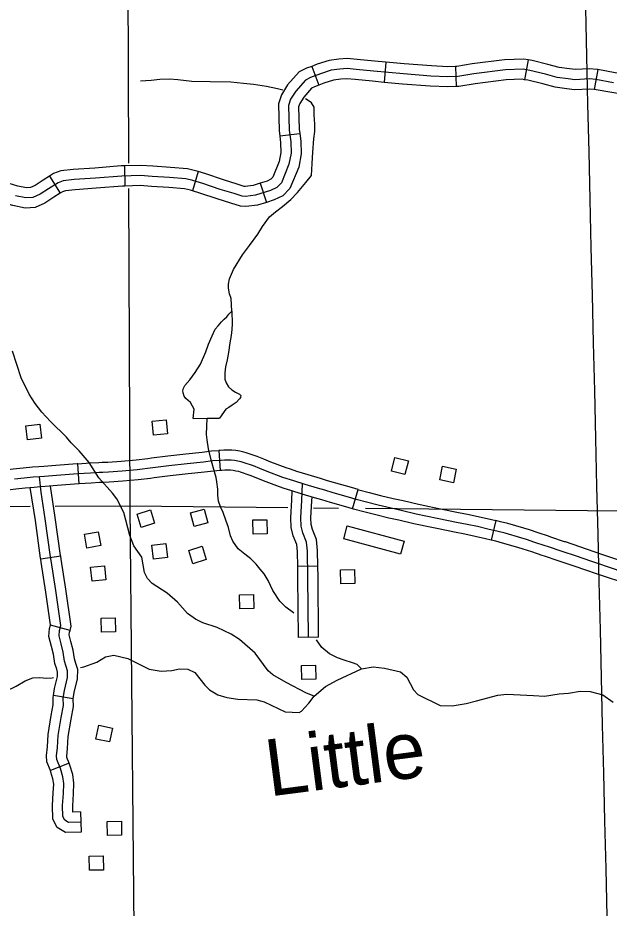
# Model space of a CAD drawing. Extents: x -19 to 366, y -4 to 359.
# Drawn here: x 134.232 to 135.065, y 193.481 to 194.735 of the extents above; entities that cross this region are included whole.
import ezdxf

# ---------------------------------------------------------------- set-up
doc = ezdxf.new("R2010")
doc.units = 0
for name, color, linetype in [('Level 31', 7, 'Continuous'), ('Level 32', 7, 'Continuous'), ('Level 35', 7, 'Continuous'), ('Level 5', 7, 'Continuous'), ('Level 56', 7, 'Continuous'), ('Level 60', 7, 'Continuous')]:
    doc.layers.add(name, color=color, linetype=linetype)

msp = doc.modelspace()

# ---------------------------------------------------------------- linework, layer by layer
at = {"layer": 'Level 31'}
for p, q in [((134.5152, 194.1259), (134.5169, 194.0975)), ((134.3179, 194.0788), (134.3161, 194.1072)), ((134.7034, 194.0436), (134.7114, 194.0709)), ((134.8015, 194.02), (134.8015, 194.02)), ((134.9057, 194.027), (134.8991, 193.9994))]:
    msp.add_line(p, q, dxfattribs=at)
for points in [[(134.4149, 194.1147), (134.4203, 194.1154), (134.4431, 194.1182), (134.4686, 194.1211), (134.4917, 194.1237), (134.5047, 194.1252), (134.5152, 194.1259)], [(134.6159, 194.0993), (134.6097, 194.1014), (134.5884, 194.1093), (134.5784, 194.1134), (134.569, 194.1174), (134.5536, 194.1225), (134.5502, 194.1235), (134.5447, 194.1248), (134.5391, 194.1257), (134.5335, 194.1263), (134.5278, 194.1265), (134.5221, 194.1264), (134.517, 194.126), (134.5152, 194.1259)], [(134.3161, 194.1072), (134.3154, 194.1071), (134.2851, 194.1047), (134.2683, 194.1034), (134.2613, 194.1029), (134.2523, 194.1022), (134.239, 194.101), (134.2252, 194.0993), (134.2175, 194.0984), (134.2156, 194.0981)], [(135.0877, 193.9536), (135.0645, 193.9613), (135.0505, 193.9659), (135.0396, 193.9697), (135.0191, 193.9767), (134.9992, 193.9834), (134.9784, 193.9904), (134.9751, 193.9915), (134.9606, 193.9964), (134.9487, 194.0003), (134.9408, 194.0029), (134.9186, 194.0092), (134.9087, 194.0117), (134.8942, 194.0152), (134.8795, 194.0185), (134.8649, 194.0216), (134.8499, 194.0246), (134.8249, 194.0296), (134.8066, 194.0334), (134.7932, 194.0363), (134.7718, 194.0414), (134.7577, 194.0446), (134.7398, 194.0488), (134.7231, 194.0529), (134.7086, 194.0569), (134.6979, 194.06), (134.6761, 194.066), (134.6642, 194.0697), (134.6539, 194.0727), (134.6367, 194.0781), (134.6206, 194.0829), (134.605, 194.0879), (134.5832, 194.0961), (134.5729, 194.1003), (134.564, 194.1041), (134.5494, 194.1089), (134.5466, 194.1097), (134.5419, 194.1108), (134.5372, 194.1116), (134.5324, 194.1121), (134.5276, 194.1123), (134.5229, 194.1122), (134.5181, 194.1118), (134.506, 194.1111), (134.4934, 194.1096), (134.4702, 194.107), (134.4447, 194.1041), (134.422, 194.1013), (134.4, 194.0985), (134.3785, 194.0966), (134.3593, 194.0955), (134.3513, 194.095), (134.3464, 194.0948), (134.3342, 194.0941), (134.3164, 194.093), (134.2862, 194.0905), (134.2693, 194.0892), (134.2623, 194.0887)], [(134.3161, 194.1072), (134.3334, 194.1083), (134.3457, 194.109), (134.3506, 194.1092), (134.3585, 194.1096), (134.3775, 194.1107), (134.3984, 194.1126), (134.4149, 194.1147)], [(134.5169, 194.0975), (134.5073, 194.0969), (134.495, 194.0955), (134.4718, 194.0929), (134.4464, 194.09), (134.4238, 194.0872), (134.4185, 194.0865)], [(134.6071, 194.0723), (134.6003, 194.0745), (134.578, 194.0829), (134.5674, 194.0872), (134.559, 194.0908), (134.5453, 194.0953), (134.543, 194.096), (134.5391, 194.0969), (134.5353, 194.0975), (134.5314, 194.0979), (134.5275, 194.0981), (134.5236, 194.098), (134.5191, 194.0976), (134.5169, 194.0975)], [(134.7114, 194.0709), (134.7018, 194.0737), (134.6801, 194.0797), (134.6683, 194.0833), (134.6581, 194.0863), (134.6409, 194.0917), (134.6248, 194.0964), (134.6159, 194.0993)], [(134.2623, 194.0887), (134.2534, 194.0881), (134.2405, 194.0869), (134.227, 194.0852)], [(134.4185, 194.0865), (134.4015, 194.0844), (134.3795, 194.0824), (134.3602, 194.0813), (134.352, 194.0808), (134.347, 194.0806), (134.3351, 194.0799), (134.3179, 194.0788)], [(134.318, 194.0788), (134.3174, 194.0788), (134.2873, 194.0763), (134.2703, 194.075), (134.2633, 194.0745), (134.2546, 194.0739), (134.242, 194.0727), (134.2287, 194.0711), (134.2211, 194.0702), (134.2193, 194.07)], [(134.7034, 194.0436), (134.694, 194.0464), (134.6722, 194.0524), (134.6601, 194.0561), (134.6498, 194.0591), (134.6326, 194.0645), (134.6163, 194.0693), (134.6071, 194.0723)], [(134.7114, 194.0709), (134.7125, 194.0706), (134.7267, 194.0667), (134.7431, 194.0626), (134.7609, 194.0584), (134.775, 194.0553), (134.7964, 194.0502), (134.8076, 194.0477)], [(134.8015, 194.02), (134.79, 194.0225), (134.7686, 194.0276), (134.7545, 194.0307), (134.7365, 194.035), (134.7196, 194.0392), (134.7048, 194.0432), (134.7034, 194.0436)], [(134.8076, 194.0477), (134.8095, 194.0473), (134.8277, 194.0436), (134.8527, 194.0386), (134.8677, 194.0355), (134.8826, 194.0324), (134.8974, 194.029), (134.9057, 194.027)], [(134.8991, 193.9994), (134.8909, 194.0014), (134.8765, 194.0046), (134.862, 194.0077), (134.8471, 194.0107), (134.8221, 194.0157), (134.8036, 194.0195), (134.8015, 194.02)], [(135.0025, 193.9973), (134.9829, 194.0039), (134.9796, 194.005), (134.9651, 194.0099), (134.9531, 194.0138), (134.9449, 194.0165), (134.9223, 194.0229), (134.9122, 194.0255), (134.9057, 194.027)], [(134.9934, 193.9704), (134.9739, 193.9769), (134.9706, 193.9781), (134.9561, 193.9829), (134.9442, 193.9868), (134.9367, 193.9893), (134.9149, 193.9954), (134.9053, 193.9979), (134.8991, 193.9994)], [(135.0972, 193.9654), (135.0922, 193.9671), (135.0689, 193.9747), (135.055, 193.9794), (135.0442, 193.9831), (135.0237, 193.9901), (135.0038, 193.9969), (135.0025, 193.9973)], [(135.0882, 193.9385), (135.0833, 193.9401), (135.06, 193.9478), (135.0459, 193.9525), (135.035, 193.9562), (135.0145, 193.9632), (134.9946, 193.97), (134.9934, 193.9704)]]:
    msp.add_lwpolyline(points, dxfattribs=at)
at = {"layer": 'Level 32'}
for p, q in [((134.7505, 194.6728), (134.748, 194.6445)), ((134.9509, 194.6762), (134.9457, 194.6483)), ((134.6459, 194.6671), (134.6561, 194.6406)), ((134.8486, 194.667), (134.8495, 194.6386)), ((135.0493, 194.6626), (135.0441, 194.6347)), ((134.6009, 194.569), (134.6291, 194.5726)), ((134.3819, 194.5268), (134.3827, 194.4984)), ((134.2764, 194.5124), (134.2913, 194.4882)), ((134.4858, 194.519), (134.4777, 194.4918)), ((134.5734, 194.5024), (134.5821, 194.4754)), ((134.2921, 193.977), (134.264, 193.9728)), ((134.6546, 193.9627), (134.6262, 193.9624)), ((134.3052, 193.8724), (134.2779, 193.8799)), ((134.6557, 193.8627), (134.6273, 193.8624)), ((134.3098, 193.7761), (134.2818, 193.7808)), ((134.3038, 193.6854), (134.2775, 193.6747)), ((134.32, 193.6165), (134.3208, 193.5881))]:
    msp.add_line(p, q, dxfattribs=at)
for points in [[(134.7505, 194.6728), (134.7346, 194.6742), (134.7102, 194.6768), (134.696, 194.6782), (134.6841, 194.6774), (134.6703, 194.6755), (134.6535, 194.67), (134.6459, 194.6671)], [(134.8486, 194.667), (134.8378, 194.6666), (134.8148, 194.6676), (134.7764, 194.6705), (134.7505, 194.6728)], [(134.9509, 194.6762), (134.945, 194.6773), (134.9179, 194.6765), (134.8723, 194.6705), (134.8505, 194.667), (134.8486, 194.667)], [(135.0493, 194.6626), (135.0481, 194.6628), (135.0377, 194.6635), (135.0177, 194.6625), (135.0094, 194.6637), (134.9948, 194.6656), (134.9788, 194.6699), (134.9565, 194.6752), (134.9509, 194.6762)], [(135.0714, 194.644), (135.0463, 194.6487), (135.0376, 194.6493), (135.017, 194.6482), (135.0075, 194.6496), (134.992, 194.6516), (134.9753, 194.6561), (134.9535, 194.6613), (134.9439, 194.6631), (134.919, 194.6623), (134.8743, 194.6564), (134.8518, 194.6529), (134.8377, 194.6524), (134.814, 194.6534), (134.7752, 194.6564), (134.7332, 194.6601), (134.7088, 194.6627), (134.6958, 194.664), (134.6855, 194.6632), (134.6735, 194.6616), (134.6583, 194.6566), (134.6444, 194.6513), (134.637, 194.6477), (134.6233, 194.6323), (134.6162, 194.6209), (134.6131, 194.6121), (134.6142, 194.5774), (134.6163, 194.5605), (134.6168, 194.5447), (134.6139, 194.5292), (134.6031, 194.5031), (134.5966, 194.4962), (134.588, 194.4922), (134.5667, 194.4854), (134.5526, 194.4837), (134.548, 194.484), (134.5364, 194.4877), (134.5171, 194.4938), (134.4924, 194.5022), (134.4785, 194.5063), (134.4685, 194.5085), (134.4456, 194.5103), (134.421, 194.5121), (134.4044, 194.5133), (134.3783, 194.5125), (134.3412, 194.5096), (134.311, 194.5075), (134.2957, 194.5058), (134.2883, 194.503), (134.2748, 194.4947), (134.263, 194.4869), (134.2528, 194.4824), (134.2428, 194.4817), (134.2282, 194.4846)], [(134.6459, 194.6671), (134.6387, 194.6643), (134.6283, 194.6593), (134.6119, 194.6409), (134.6033, 194.627), (134.5989, 194.6142), (134.6, 194.5763), (134.6009, 194.569)], [(135.1411, 194.6527), (135.1334, 194.6504), (135.1278, 194.6497), (135.1102, 194.6521), (135.0738, 194.658), (135.0493, 194.6626)], [(134.748, 194.6445), (134.7318, 194.646), (134.7073, 194.6486), (134.6956, 194.6497), (134.6869, 194.6491), (134.6767, 194.6477), (134.663, 194.6432), (134.6561, 194.6406)], [(134.9457, 194.6483), (134.9428, 194.6488), (134.9202, 194.6482), (134.8764, 194.6424), (134.8531, 194.6387), (134.8495, 194.6386)], [(135.0445, 194.6346), (135.0374, 194.635), (135.0164, 194.634), (135.0055, 194.6355), (134.9893, 194.6377), (134.9718, 194.6424), (134.9506, 194.6474), (134.9457, 194.6483)], [(134.6561, 194.6406), (134.65, 194.6382), (134.6457, 194.6362), (134.6347, 194.6238), (134.6291, 194.6147), (134.6274, 194.6099), (134.6283, 194.5786), (134.6291, 194.5726)], [(134.8495, 194.6386), (134.8376, 194.6382), (134.8131, 194.6392), (134.7741, 194.6422), (134.748, 194.6445)], [(135.1492, 194.6254), (135.1393, 194.6225), (135.1276, 194.621), (135.106, 194.624), (135.0689, 194.6301), (135.0441, 194.6347)], [(134.6291, 194.5726), (134.6305, 194.5616), (134.631, 194.5436), (134.6276, 194.5251), (134.6152, 194.4952), (134.6051, 194.4845), (134.5932, 194.479), (134.5821, 194.4754)], [(134.6009, 194.569), (134.6021, 194.5593), (134.6025, 194.5458), (134.6002, 194.5332), (134.591, 194.5109), (134.5882, 194.508), (134.5829, 194.5055), (134.5734, 194.5024)], [(134.3819, 194.5268), (134.3775, 194.5267), (134.3402, 194.5238), (134.3097, 194.5216), (134.2924, 194.5197), (134.282, 194.5159), (134.2764, 194.5124)], [(134.4858, 194.519), (134.4821, 194.5201), (134.4706, 194.5226), (134.4467, 194.5245), (134.4221, 194.5263), (134.4047, 194.5275), (134.3819, 194.5268)], [(134.2764, 194.5124), (134.2672, 194.5067), (134.2562, 194.4994), (134.2493, 194.4964), (134.2437, 194.496), (134.2315, 194.4984), (134.2194, 194.5019), (134.206, 194.5064), (134.1926, 194.5085)], [(134.5734, 194.5024), (134.5636, 194.4993), (134.5522, 194.4979), (134.5507, 194.498), (134.5407, 194.5012), (134.5216, 194.5073), (134.4967, 194.5157), (134.4858, 194.519)], [(134.3827, 194.4984), (134.379, 194.4983), (134.3423, 194.4955), (134.3123, 194.4933), (134.299, 194.4918), (134.2945, 194.4902), (134.2913, 194.4882)], [(134.4777, 194.4918), (134.475, 194.4926), (134.4664, 194.4944), (134.4445, 194.4962), (134.42, 194.4979), (134.4041, 194.499), (134.3827, 194.4984)], [(134.2913, 194.4882), (134.2825, 194.4828), (134.2698, 194.4744), (134.2562, 194.4684), (134.2419, 194.4674), (134.2248, 194.4708), (134.211, 194.4748), (134.1992, 194.4787), (134.1882, 194.4805)], [(134.5821, 194.4754), (134.5697, 194.4714), (134.553, 194.4694), (134.5454, 194.4699), (134.5321, 194.4742), (134.5127, 194.4803), (134.488, 194.4886), (134.4777, 194.4918)], [(134.3204, 193.6023), (134.3029, 193.6018), (134.298, 193.6048), (134.2952, 193.61), (134.2948, 193.6254), (134.2958, 193.6427), (134.2965, 193.6565), (134.2951, 193.666), (134.2916, 193.6776), (134.2865, 193.6902), (134.2863, 193.6955), (134.2875, 193.7072), (134.2886, 193.7242), (134.2926, 193.7498), (134.2958, 193.7664), (134.2955, 193.777), (134.2973, 193.7876), (134.3015, 193.8058), (134.3018, 193.8153), (134.3, 193.8217), (134.2976, 193.829), (134.2957, 193.8417), (134.2927, 193.8533), (134.2897, 193.8649), (134.2905, 193.8724), (134.2924, 193.8793), (134.2851, 193.9285), (134.2787, 193.9706), (134.2779, 193.976), (134.2704, 194.0294), (134.2645, 194.0669), (134.2623, 194.0887)], [(134.264, 193.9728), (134.2638, 193.974), (134.2564, 194.0273), (134.2491, 194.0736)], [(134.2921, 193.977), (134.2919, 193.978), (134.2845, 194.0315), (134.2776, 194.0755)], [(134.6262, 193.9624), (134.6259, 193.9831), (134.6248, 193.9933), (134.62, 194.0056), (134.617, 194.0174), (134.6165, 194.0314), (134.6179, 194.0559), (134.6183, 194.0687)], [(134.6415, 193.8626), (134.6406, 193.9471), (134.6401, 193.984), (134.6387, 193.9967), (134.6335, 194.01), (134.6312, 194.0194), (134.6307, 194.0312), (134.6321, 194.0553), (134.6328, 194.0792)], [(134.6546, 193.9627), (134.6543, 193.9849), (134.6526, 194.0002), (134.6471, 194.0143), (134.6453, 194.0214), (134.6449, 194.0311), (134.6463, 194.0547), (134.6464, 194.0602)], [(134.2779, 193.8799), (134.2779, 193.8802), (134.2711, 193.9264), (134.2646, 193.9685), (134.264, 193.9728)], [(134.3052, 193.8724), (134.3069, 193.8785), (134.2992, 193.9306), (134.2927, 193.9728), (134.2921, 193.977)], [(134.6273, 193.8624), (134.6264, 193.947), (134.6262, 193.9624)], [(134.6557, 193.8627), (134.6548, 193.9473), (134.6546, 193.9627)], [(134.2818, 193.7808), (134.2834, 193.7904), (134.2874, 193.8076), (134.2875, 193.8136), (134.2864, 193.8176), (134.2838, 193.8257), (134.2817, 193.8388), (134.2789, 193.8497), (134.2753, 193.8639), (134.2765, 193.8751), (134.2779, 193.8799)], [(134.3098, 193.7761), (134.3112, 193.7848), (134.3157, 193.804), (134.316, 193.8171), (134.3136, 193.8258), (134.3115, 193.8323), (134.3096, 193.8446), (134.3064, 193.8568), (134.3041, 193.866), (134.3045, 193.8697), (134.3052, 193.8724)], [(134.2775, 193.6747), (134.2723, 193.6872), (134.2721, 193.696), (134.2734, 193.7084), (134.2745, 193.7258), (134.2786, 193.7523), (134.2816, 193.7675), (134.2813, 193.7779), (134.2818, 193.7808)], [(134.3038, 193.6854), (134.3006, 193.6932), (134.3005, 193.695), (134.3017, 193.706), (134.3027, 193.7227), (134.3066, 193.7474), (134.3101, 193.7652), (134.3097, 193.776), (134.3098, 193.7761)], [(134.32, 193.6165), (134.3093, 193.6162), (134.309, 193.6252), (134.31, 193.642), (134.3107, 193.6572), (134.309, 193.6691), (134.305, 193.6824), (134.3038, 193.6854)], [(134.3208, 193.5881), (134.299, 193.5875), (134.2873, 193.5948), (134.2811, 193.6063), (134.2806, 193.6256), (134.2816, 193.6435), (134.2822, 193.6559), (134.2812, 193.663), (134.2782, 193.6728), (134.2775, 193.6747)]]:
    msp.add_lwpolyline(points, dxfattribs=at)
at = {"layer": 'Level 35'}
for points in [[(134.6053, 194.6337), (134.5979, 194.6354), (134.582, 194.6385), (134.564, 194.6417), (134.5498, 194.6429), (134.5319, 194.6447), (134.503, 194.6452), (134.4767, 194.6457), (134.4574, 194.6481), (134.4455, 194.649), (134.4319, 194.6487), (134.4196, 194.6473), (134.4047, 194.6464)], [(134.6454, 194.5133), (134.6467, 194.5304), (134.6476, 194.5464), (134.6491, 194.565), (134.6503, 194.5753), (134.6505, 194.5857), (134.6496, 194.5988), (134.6492, 194.6098), (134.6456, 194.6157), (134.641, 194.6191), (134.637, 194.6212)], [(134.5864, 194.4552), (134.5947, 194.4623), (134.6047, 194.4698), (134.6164, 194.4795), (134.6258, 194.4894), (134.6377, 194.5035), (134.6454, 194.5133)], [(134.5333, 194.322), (134.5323, 194.34), (134.5299, 194.3464), (134.5288, 194.3545), (134.5285, 194.3604), (134.5298, 194.3676), (134.5357, 194.3809), (134.5483, 194.4014), (134.5582, 194.4147), (134.5698, 194.4305), (134.5767, 194.4413), (134.5864, 194.4552)], [(134.4789, 194.171), (134.4803, 194.1839), (134.4779, 194.1884), (134.475, 194.1936), (134.4686, 194.199), (134.4661, 194.2024), (134.4645, 194.2069), (134.4642, 194.2099), (134.4654, 194.2137), (134.4672, 194.2176), (134.4742, 194.2255), (134.4816, 194.2355), (134.4892, 194.2473), (134.4968, 194.2649), (134.5005, 194.2756), (134.5054, 194.2872), (134.5099, 194.2968), (134.5141, 194.3015), (134.5189, 194.3069), (134.5226, 194.311), (134.5265, 194.3143), (134.5289, 194.3177), (134.5333, 194.322), (134.5337, 194.3042), (134.5333, 194.2964), (134.5326, 194.2877), (134.5303, 194.2776), (134.5287, 194.2639), (134.5269, 194.2534), (134.5243, 194.2439), (134.5235, 194.2351), (134.5235, 194.2264), (134.5252, 194.2213), (134.5287, 194.2155), (134.5333, 194.2111), (134.5385, 194.208), (134.5439, 194.2054), (134.546, 194.2034), (134.5453, 194.2003), (134.544, 194.1988), (134.5396, 194.1934), (134.5336, 194.1896), (134.5292, 194.1863), (134.5249, 194.1839), (134.5161, 194.1714)], [(134.6494, 193.7797), (134.6384, 193.7837), (134.6099, 193.799), (134.5909, 193.8098), (134.5844, 193.8154), (134.566, 193.8403), (134.5439, 193.8597), (134.5325, 193.8668), (134.5127, 193.8765), (134.4923, 193.8831), (134.482, 193.8883), (134.4706, 193.8962), (134.4568, 193.9123), (134.4423, 193.9247), (134.421, 193.9385), (134.4142, 193.9453), (134.4103, 193.954), (134.4063, 193.9755), (134.3952, 193.9917), (134.3894, 194.0061), (134.3812, 194.0386), (134.3712, 194.0578), (134.365, 194.0657), (134.3459, 194.0871), (134.3321, 194.109), (134.318, 194.1255), (134.3069, 194.1364), (134.3004, 194.1447), (134.2775, 194.1668), (134.2657, 194.1796), (134.2561, 194.192), (134.2477, 194.2052), (134.2365, 194.2282), (134.224, 194.266)], [(134.4789, 194.171), (134.4985, 194.1714), (134.5161, 194.1714)], [(134.6206, 193.8967), (134.6204, 193.8969), (134.6094, 193.9052), (134.6009, 193.9137), (134.5913, 193.9286), (134.5846, 193.9425), (134.579, 193.9521), (134.5734, 193.9588), (134.5678, 193.9655), (134.5599, 193.9733), (134.5518, 193.9797), (134.5422, 193.9873), (134.5347, 193.9983), (134.5313, 194.0058), (134.5284, 194.0175), (134.525, 194.0275), (134.521, 194.0386), (134.5174, 194.0465), (134.5147, 194.0546), (134.5134, 194.0627), (134.5134, 194.0712), (134.5124, 194.0818), (134.5112, 194.0879), (134.5091, 194.0958), (134.5048, 194.1107), (134.5002, 194.128), (134.4984, 194.1407), (134.4975, 194.1483), (134.4985, 194.1714)], [(134.7159, 193.8182), (134.7101, 193.8243), (134.7034, 193.8268), (134.6918, 193.8306), (134.6824, 193.8336), (134.6708, 193.8392), (134.66, 193.8484), (134.6529, 193.8592)], [(134.3199, 193.8202), (134.3246, 193.8208), (134.3431, 193.8275), (134.3551, 193.8352), (134.3668, 193.8375), (134.3865, 193.8328), (134.4169, 193.8176), (134.4336, 193.8147), (134.4487, 193.8156), (134.4596, 193.8184), (134.4713, 193.8177), (134.4812, 193.8129), (134.4954, 193.7952), (134.5018, 193.7888), (134.5136, 193.7814), (134.5261, 193.7777), (134.542, 193.7756), (134.5685, 193.7747), (134.5791, 193.7718), (134.6087, 193.7577), (134.628, 193.7567), (134.6314, 193.7586), (134.6419, 193.7697), (134.6494, 193.7797), (134.6655, 193.7931), (134.6817, 193.802), (134.7159, 193.8182), (134.7325, 193.821), (134.7484, 193.8193), (134.7712, 193.8138), (134.7799, 193.8063), (134.7895, 193.7886), (134.7956, 193.7819), (134.8272, 193.7666), (134.8438, 193.766), (134.8638, 193.7693), (134.8781, 193.7732), (134.9083, 193.7811), (134.9212, 193.7823), (134.9586, 193.7804), (134.9741, 193.7798), (134.9949, 193.7831), (135.0077, 193.7839), (135.0243, 193.7868), (135.0383, 193.7861), (135.0561, 193.7814)], [(134.021, 193.7053), (134.0505, 193.7082), (134.0705, 193.708), (134.0993, 193.7053), (134.1144, 193.7062), (134.1249, 193.7105), (134.1366, 193.7193), (134.1699, 193.7499), (134.18, 193.7622), (134.1987, 193.779), (134.2292, 193.7937), (134.242, 193.8011), (134.2526, 193.8053), (134.2624, 193.8062), (134.2726, 193.8048), (134.2802, 193.8056), (134.2819, 193.8061)], [(135.0561, 193.7814), (135.071, 193.7714)]]:
    msp.add_lwpolyline(points, dxfattribs=at)
at = {"layer": 'Level 5'}
for points in [[(134.3857, 195.0473), (134.3877, 194.5307)], [(134.3878, 194.4948), (134.3896, 194.0472)], [(134.2491, 194.0469), (133.84, 194.0459)], [(134.3896, 194.0472), (134.2841, 194.0469)], [(134.3896, 194.0472), (134.3989, 193.0554)], [(134.6123, 194.045), (134.3896, 194.0472)], [(134.6835, 194.0443), (134.6486, 194.0446)], [(135.124, 194.04), (134.7216, 194.0439)]]:
    msp.add_lwpolyline(points, dxfattribs=at)
at = {"layer": 'Level 56'}
for points in [[(134.4209, 194.1673), (134.4406, 194.1691), (134.4424, 194.1494), (134.4228, 194.1476)], [(134.2429, 194.1606), (134.2625, 194.1631), (134.265, 194.1434), (134.2454, 194.1409)], [(134.7631, 194.1161), (134.7822, 194.1112), (134.7773, 194.092), (134.7582, 194.0969)], [(134.8304, 194.1037), (134.8497, 194.0996), (134.8456, 194.0803), (134.8263, 194.0843)], [(134.4244, 194.0232), (134.4055, 194.0174), (134.3997, 194.0363), (134.4186, 194.0421)], [(134.4993, 194.024), (134.4803, 194.0189), (134.4751, 194.0379), (134.4941, 194.0431)], [(134.5831, 194.0085), (134.5634, 194.0081), (134.563, 194.0279), (134.5827, 194.0283)], [(134.6912, 194.0013), (134.6961, 194.0196), (134.7761, 193.9982), (134.7712, 193.9799)], [(134.3254, 194.0078), (134.3448, 194.0114), (134.3485, 193.992), (134.3291, 193.9883)], [(134.4206, 193.9924), (134.4402, 193.9949), (134.4427, 193.9752), (134.4231, 193.9728)], [(134.4725, 193.9849), (134.4913, 193.9908), (134.4972, 193.972), (134.4784, 193.9661)], [(134.3342, 193.9612), (134.3538, 193.9632), (134.3558, 193.9435), (134.3362, 193.9415)], [(134.7066, 193.9385), (134.6869, 193.9381), (134.6865, 193.9578), (134.7062, 193.9582)], [(134.5641, 193.903), (134.5444, 193.9026), (134.544, 193.9223), (134.5637, 193.9227)], [(134.3691, 193.8703), (134.3494, 193.8699), (134.349, 193.8897), (134.3687, 193.8901)], [(134.6518, 193.8036), (134.6321, 193.8032), (134.6317, 193.823), (134.6514, 193.8234)], [(134.3456, 193.7386), (134.3649, 193.7345), (134.3609, 193.7152), (134.3416, 193.7192)], [(134.3779, 193.5836), (134.3582, 193.5832), (134.3578, 193.603), (134.3776, 193.6034)], [(134.3522, 193.5347), (134.3325, 193.5343), (134.3321, 193.5541), (134.3518, 193.5545)]]:
    msp.add_lwpolyline(points, close=True, dxfattribs=at)
at = {"layer": 'Level 60'}
for points in [[(139.4406, 1.5315), (139.2511, 10.1473), (139.0608, 18.7633), (138.8699, 27.3793), (138.6784, 35.9956), (138.4861, 44.6119), (138.2932, 53.2285), (138.0997, 61.8451), (137.9055, 70.4619), (137.7106, 79.0789), (137.5151, 87.6959), (137.319, 96.3132), (137.1221, 104.9306), (136.9247, 113.5481), (136.7265, 122.1658), (136.5278, 130.7836), (136.3283, 139.4016), (136.1282, 148.0197), (135.9275, 156.6379), (135.7261, 165.2564), (135.5241, 173.8749), (135.3214, 182.4936), (135.1181, 191.1125), (134.9141, 199.7315), (134.7095, 208.3506), (134.5043, 216.9699), (134.2984, 225.5894), (134.0919, 234.209), (133.8847, 242.8288), (133.6769, 251.4487), (133.4685, 260.0687), (133.2594, 268.6889), (133.0497, 277.3093), (132.8393, 285.9298), (132.6283, 294.5504), (132.4167, 303.1713), (132.2044, 311.7922), (131.9916, 320.4133), (131.778, 329.0346), (131.5639, 337.656), (131.3491, 346.2776)], [(0, 189.5162), (7.1121, 189.5206), (14.2243, 189.5339), (21.3364, 189.556), (28.4484, 189.5869), (35.5605, 189.6267), (42.6725, 189.6754), (49.7844, 189.7329), (56.8962, 189.7992), (64.0079, 189.8744), (71.1196, 189.9584), (78.2311, 190.0512), (85.3425, 190.1529), (92.4538, 190.2635), (99.5649, 190.3829), (106.6759, 190.5111), (113.7867, 190.6482), (120.8974, 190.7941), (128.0078, 190.9489), (135.1181, 191.1125), (142.2282, 191.2849), (149.338, 191.4662), (156.4476, 191.6563), (163.5569, 191.8553), (170.666, 192.0631), (177.7749, 192.2798), (184.8835, 192.5053), (191.9917, 192.7396), (199.0997, 192.9828), (206.2074, 193.2348), (213.3147, 193.4956), (220.4218, 193.7653), (227.5285, 194.0438), (234.6348, 194.3312), (241.7408, 194.6274), (248.8464, 194.9324), (255.9516, 195.2463), (263.0564, 195.569), (270.1608, 195.9005), (277.2648, 196.2409), (284.3683, 196.5901), (291.4715, 196.9481), (298.5741, 197.315), (305.6763, 197.6907), (312.7781, 198.0753), (319.8793, 198.4686), (326.9801, 198.8708), (334.0804, 199.2818), (341.1801, 199.7017)]]:
    msp.add_spline(points, degree=3, dxfattribs=at)

# ---------------------------------------------------------------- texts
at = {"layer": 'Level 35'}
msp.add_text('Little', height=0.08, rotation=7.3869, dxfattribs=at).set_placement((134.5861, 193.6382))

doc.saveas('drawing.dxf')
